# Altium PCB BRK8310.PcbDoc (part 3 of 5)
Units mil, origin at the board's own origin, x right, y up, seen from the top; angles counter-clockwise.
Board outline 6600.39 x 4492.13 mil, 4 copper layers (L1-Top, L2-GND, L3-GND, L4-BOT), stack 60.25 mil thick; 119 components, 266 nets, 1026 pads, 596 vias.
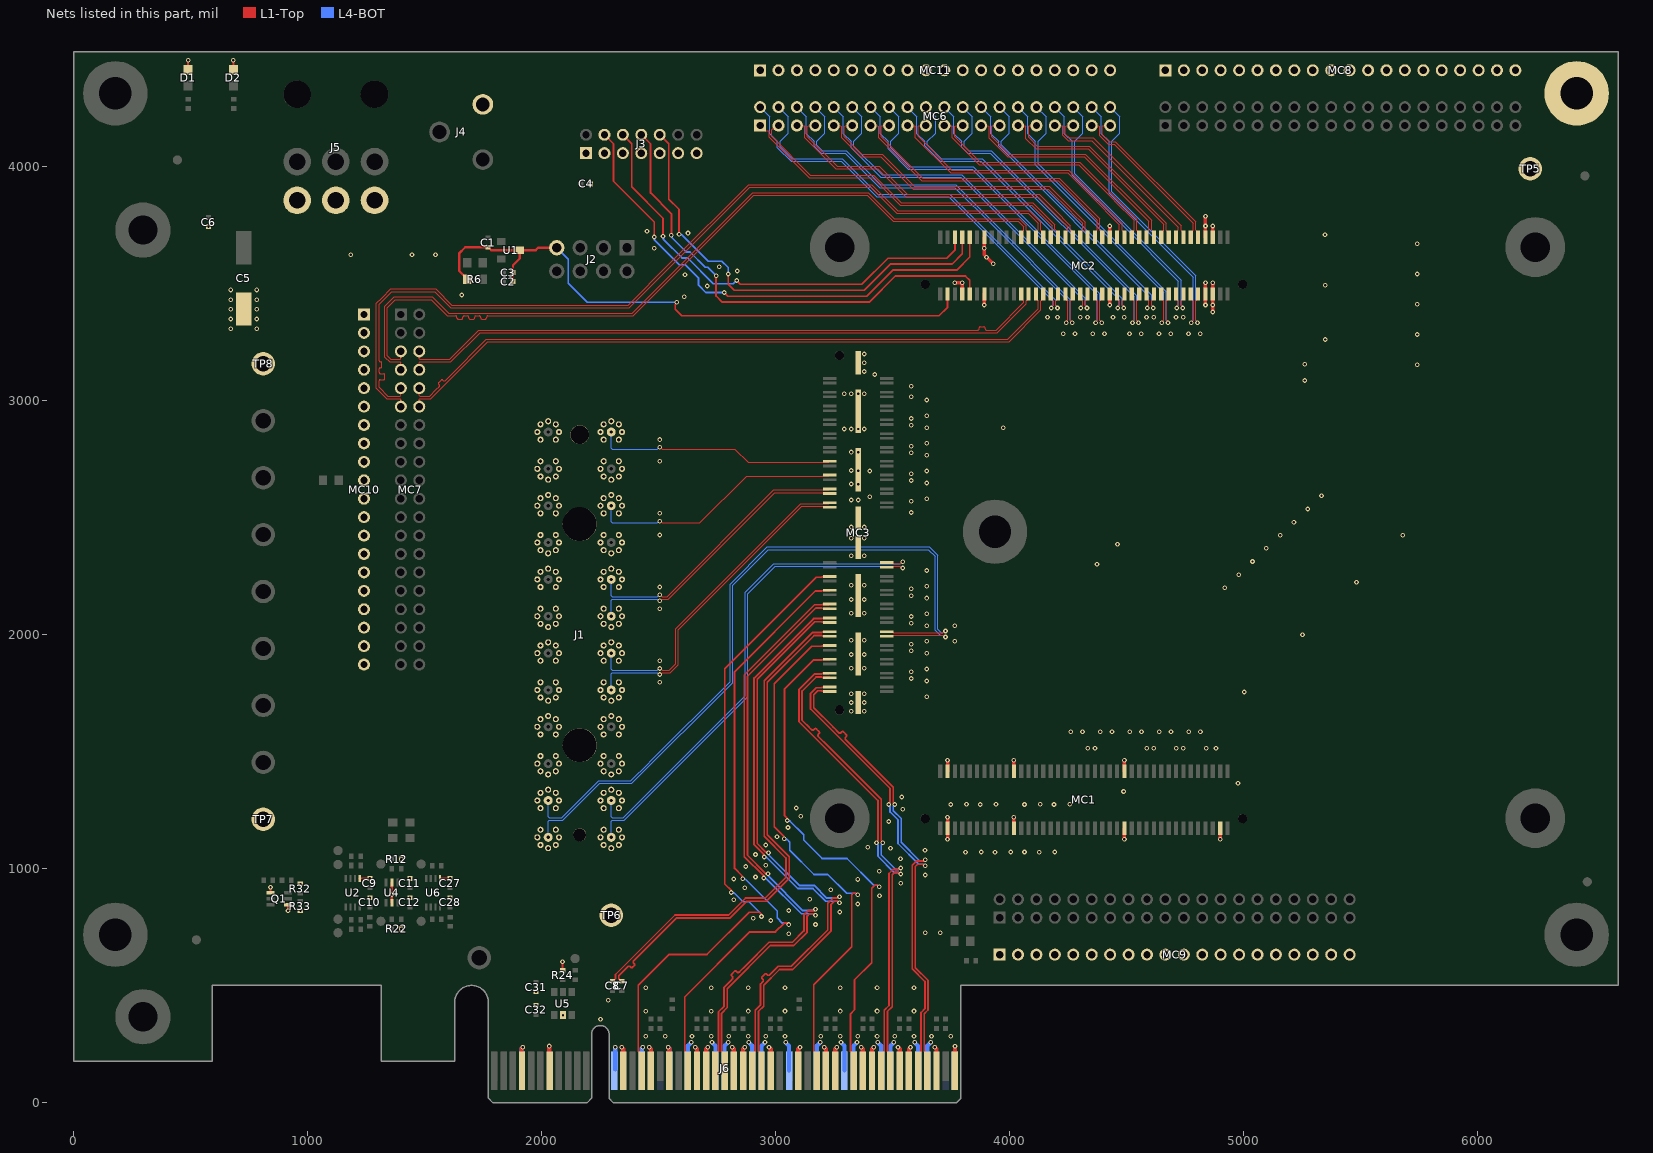
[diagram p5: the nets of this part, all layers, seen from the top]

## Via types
v1: diameter 20, hole 10, L1-Top to L4-BOT, tented both sides, 596 vias

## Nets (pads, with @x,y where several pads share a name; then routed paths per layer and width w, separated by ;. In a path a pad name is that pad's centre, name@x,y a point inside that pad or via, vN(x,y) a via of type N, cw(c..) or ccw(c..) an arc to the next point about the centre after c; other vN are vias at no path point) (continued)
B86_L1N: MC2.57 MC7.6 | length 2775
  L1-Top w5.25: MC7.6@1476.37,3212.12 1476.37,3181.45 1479.45,3178.38 1519.68,3178.38 1606.74,3178.38 1731.51,3303.15 3828.73,3303.15 3864.26,3303.15 ccw(c3864.26,3308.4) 3869.51,3308.4 3869.51,3311.84 cw(c3874.56,3311.84) 3874.56,3316.89 3889.71,3316.89 cw(c3889.71,3311.84) 3894.76,3311.84 3894.76,3308.4 ccw(c3900.01,3308.4) 3900.01,3303.15 3927.89,3303.15 3941.61,3303.15 4059.33,3420.86 4059.33,3428.29 4056.25,3431.36 4055.63,3431.36 4049.2,3437.79 MC2.57@4049.2,3457.28
B86_L1P: MC2.55 MC7.8 | length 2775
  L1-Top w5.25: MC7.8@1476.37,3133.38 1476.37,3164.05 1479.45,3167.13 1519.68,3167.13 1611.4,3167.13 1736.17,3291.9 3946.27,3291.9 4070.58,3416.2 4070.58,3428.29 4073.65,3431.36 4074.27,3431.36 4080.7,3437.79 MC2.55@4080.7,3457.28
B86_L2N: MC2.50 MC6.1 | length 1491.4
  L1-Top w5.25: MC6.1@2933.06,4177.16 2956.03,4154.2 2968.03,4154.2 2971.1,4151.12 2971.1,4127.03 3143.69,3954.44 3414.62,3954.44 3532.34,3836.72 4093.68,3836.72 4181.64,3748.75 4181.64,3748.03 4181.64,3729.19 ; MC2.50@4175.19,3700.2 4181.62,3706.63 4181.62,3729.17
B86_L2P: MC2.48 MC6.3 | length 1490.5
  L1-Top w5.25: MC6.3@3011.8,4177.16 3000.39,4177.16 2982.35,4159.13 2982.35,4131.69 3148.35,3965.69 3419.28,3965.69 3537,3847.97 4098.34,3847.97 4192.89,3753.41 4192.89,3748.03 4192.89,3733.48 4206.69,3719.68 MC2.48@4206.69,3700.2
B86_L3N: MC2.49 MC6.2 | length 1753
  L1-Top w5.25: MC2.49@4175.19,3457.28 4175.19,3437.79 4181.62,3431.36 4182.24,3431.36 4185.31,3428.29 4185.31,3408.12 4177.94,3400.74 v1(4177.94,3397.64)
  L4-BOT w5.25: MC6.2@2933.06,4255.9 2973.6,4215.36 2973.6,4142.92 3007.33,4109.19 3007.33,4082.78 3065.58,4024.53 3279.96,4024.53 3431.64,3872.86 3739.11,3872.86 4185.31,3426.65 4185.31,3408.09 4177.94,3400.71 v1(4177.94,3397.64)
B86_L3P: MC2.47 MC6.4 | length 1753.4
  L1-Top w5.25: v1(4203.94,3397.64) 4203.94,3400.74 4196.56,3408.12 4196.56,3428.29 4199.64,3431.36 4200.25,3431.36 4206.69,3437.79 MC2.47@4206.69,3457.28
  L4-BOT w5.25: MC6.4@3011.8,4255.9 3052.9,4214.8 3052.9,4143.46 3018.58,4109.14 3018.58,4087.44 3070.24,4035.78 3284.62,4035.78 3436.3,3884.11 3743.77,3884.11 4196.56,3431.31 4196.56,3408.09 4203.94,3400.71 v1(4203.94,3397.64)
B86_L4N: MC2.45 MC6.6 | length 1782.6
  L1-Top w5.25: MC2.45@4238.18,3457.28 4238.18,3437.79 4244.61,3431.36 4245.23,3431.36 4248.3,3428.29 4248.3,3345.1 4240.93,3337.72 v1(4240.93,3334.64)
  L4-BOT w5.25: MC6.6@3090.54,4255.9 3131.08,4215.36 3131.08,4142.92 3164.81,4109.19 3164.81,4088.01 3193.78,4059.03 3297.33,4059.03 3444.14,3912.23 3764.84,3912.23 3929.04,3748.03 4248.3,3428.76 4248.3,3409.45 4248.3,3345.1 4240.93,3337.72 v1(4240.93,3334.64)
B86_L4P: MC2.43 MC6.8 | length 1783.1
  L1-Top w5.25: v1(4266.93,3334.64) 4266.93,3337.72 4259.55,3345.1 4259.55,3428.29 4262.63,3431.36 4263.25,3431.36 4269.68,3437.79 MC2.43@4269.68,3457.28
  L4-BOT w5.25: MC6.8@3169.28,4255.9 3210.38,4214.8 3210.38,4143.46 3176.06,4109.14 3176.06,4092.67 3198.44,4070.28 3301.99,4070.28 3448.8,3923.48 3769.5,3923.48 3944.95,3748.03 4259.55,3433.42 4259.55,3409.45 4259.55,3345.1 4266.93,3337.72 v1(4266.93,3334.64)
B86_L5N_HDGC: MC2.58 MC7.5 | length 3437.1
  L1-Top w5.25: MC7.5@1397.63,3212.12 1397.63,3181.45 1394.55,3178.38 1368.55,3178.38 1354.26,3178.38 1352.9,3179.74 1340.16,3192.48 1340.16,3399.21 1374.04,3433.09 1527.54,3433.09 1593.68,3366.95 1596.98,3363.65 1604.33,3363.65 1632.21,3363.65 cw(c1632.21,3358.4) 1637.46,3358.4 1637.46,3354.89 ccw(c1642.51,3354.89) 1642.51,3349.84 1657.66,3349.84 ccw(c1657.66,3354.89) 1662.71,3354.89 1662.71,3358.6 cw(c1667.76,3358.6) 1667.76,3363.65 1682.91,3363.65 cw(c1682.91,3358.6) 1687.96,3358.6 1687.96,3354.89 ccw(c1693.01,3354.89) 1693.01,3349.84 1708.16,3349.84 ccw(c1708.16,3354.89) 1713.21,3354.89 1713.21,3358.6 cw(c1718.26,3358.6) 1718.26,3363.65 1733.41,3363.65 cw(c1733.41,3358.6) 1738.46,3358.6 1738.46,3355.28 ccw(c1743.51,3355.28) 1743.51,3350.23 1758.66,3350.23 ccw(c1758.66,3355.28) 1763.71,3355.28 1763.71,3358.4 cw(c1768.96,3358.4) 1768.96,3363.65 1798.73,3363.65 2391.03,3363.65 2905.84,3878.47 3391.52,3878.47 3502.27,3767.72 4035.43,3767.72 4059.33,3743.81 4059.33,3729.19 4056.25,3726.11 4055.63,3726.11 4049.2,3719.68 MC2.58@4049.2,3700.2
B86_L5P_HDGC: MC2.56 MC7.7 | length 3437.1
  L1-Top w5.25: MC7.7@1397.63,3133.38 1397.63,3164.05 1394.55,3167.13 1363.89,3167.13 1349.6,3167.13 1328.91,3187.82 1328.91,3403.87 1369.38,3444.34 1532.2,3444.34 1601.64,3374.9 1798.73,3374.9 2386.37,3374.9 2901.18,3889.72 3396.18,3889.72 3506.93,3778.97 4040.09,3778.97 4070.58,3748.47 4070.58,3729.19 4073.65,3726.11 4074.27,3726.11 4080.7,3719.68 MC2.56@4080.7,3700.2
B86_L6N_HDGC: MC2.54 MC7.9 | length 3760.2
  L1-Top w5.25: MC7.9@1397.63,3054.64 1397.63,3023.97 1394.55,3020.9 1342.13,3020.9 1304.72,3058.31 1304.72,3086.19 cw(c1309.97,3086.19) 1309.97,3091.44 1324.48,3091.44 ccw(c1324.48,3096.49) 1329.53,3096.49 1329.53,3111.64 ccw(c1324.48,3111.64) 1324.48,3116.69 1309.77,3116.69 cw(c1309.77,3121.74) 1304.72,3121.74 1304.72,3136.89 cw(c1309.77,3136.89) 1309.77,3141.94 1311.58,3141.94 ccw(c1311.58,3146.99) 1316.63,3146.99 1316.63,3162.14 ccw(c1311.58,3162.14) 1311.58,3167.19 1309.97,3167.19 cw(c1309.97,3172.44) 1304.72,3172.44 1304.72,3181.41 1304.72,3412.57 1322.7,3430.55 1326,3433.84 1359.75,3467.59 1541.83,3467.59 1611.27,3398.15 2374.27,3398.15 2889.09,3912.97 3405.81,3912.97 3516.56,3802.22 4079.39,3802.22 4122.32,3759.28 4122.32,3729.19 4119.24,3726.11 4118.63,3726.11 4112.2,3719.68 MC2.54@4112.2,3700.2
B86_L6P_HDGC: MC2.52 MC7.11 | length 3760.2
  L1-Top w5.25: MC7.11@1397.63,2975.9 1397.63,3006.57 1394.55,3009.65 1350.39,3009.65 1337.47,3009.65 1293.47,3053.65 1293.47,3181.41 1293.47,3417.23 1318.04,3441.8 1355.09,3478.84 1546.49,3478.84 1615.93,3409.4 2369.61,3409.4 2549.96,3589.75 2884.43,3924.22 3410.47,3924.22 3521.22,3813.47 4084.05,3813.47 4133.57,3763.94 4133.57,3729.19 4136.65,3726.11 4137.26,3726.11 4143.69,3719.68 MC2.52@4143.69,3700.2
B86_L7N_HDGC: MC2.42 MC6.9 | length 1329
  L1-Top w5.25: MC6.9@3248.02,4177.16 3278.69,4177.16 3281.77,4174.09 3281.77,4124.84 3363.3,4043.31 3449.51,4043.31 3587.1,3905.72 4165.14,3905.72 4259.75,3811.1 4267.71,3803.15 4311.3,3759.56 4311.3,3729.19 4308.22,3726.11 4307.6,3726.11 4301.17,3719.68 MC2.42@4301.17,3700.2
B86_L7P_HDGC: MC2.40 MC6.11 | length 1329
  L1-Top w5.25: MC6.11@3326.76,4177.16 3296.09,4177.16 3293.02,4174.09 3293.02,4129.5 3367.96,4054.56 3454.17,4054.56 3591.76,3916.97 4169.8,3916.97 4322.55,3764.22 4322.55,3729.19 4325.62,3726.11 4326.24,3726.11 4332.67,3719.68 MC2.40@4332.67,3700.2
B86_L8N_HDGC: MC2.41 MC6.10 | length 1568.6
  L1-Top w5.25: MC2.41@4301.17,3457.28 4301.17,3437.79 4307.6,3431.36 4308.22,3431.36 4311.3,3428.29 4311.3,3408.12 4303.92,3400.74 v1(4303.92,3397.64)
  L4-BOT w5.25: MC6.10@3248.02,4255.9 3288.56,4215.36 3288.56,4142.92 3322.29,4109.19 3322.29,4082.87 3449.62,3955.53 3790.29,3955.53 4311.3,3434.52 4311.3,3408.09 4303.92,3400.71 v1(4303.92,3397.64)
B86_L8P_HDGC: MC2.39 MC6.12 | length 1569
  L1-Top w5.25: v1(4329.92,3397.64) 4329.92,3400.74 4322.55,3408.12 4322.55,3428.29 4325.62,3431.36 4326.24,3431.36 4332.67,3437.79 MC2.39@4332.67,3457.28
  L4-BOT w5.25: MC6.12@3326.76,4255.9 3367.86,4214.8 3367.86,4143.46 3333.54,4109.14 3333.54,4087.53 3454.28,3966.78 3794.95,3966.78 4322.55,3439.18 4322.55,3408.09 4329.92,3400.71 v1(4329.92,3397.64)
B86_L9N: MC2.53 MC7.10 | length 2919.2
  L1-Top w5.25: MC7.10@1476.37,3054.64 1476.37,3023.97 1479.45,3020.9 1521.01,3020.9 1549.67,3049.56 1561.74,3061.63 ccw(c1558.02,3065.34) 1561.74,3069.05 1559.3,3071.48 cw(c1562.88,3075.05) 1559.3,3078.62 1570.02,3089.34 cw(c1573.59,3085.77) 1577.16,3089.34 1579.59,3086.9 ccw(c1583.3,3090.62) 1587.02,3086.9 1606.73,3106.62 1763.48,3263.37 3992.23,3263.37 4122.32,3393.46 4122.32,3428.29 4119.24,3431.36 4118.63,3431.36 4112.2,3437.79 MC2.53@4112.2,3457.28
B86_L9P: MC2.51 MC7.12 | length 2919.2
  L1-Top w5.25: MC7.12@1476.37,2975.9 1476.37,3006.57 1479.45,3009.65 1525.67,3009.65 1768.14,3252.12 3996.89,3252.12 4133.57,3388.8 4133.57,3428.29 4136.65,3431.36 4137.26,3431.36 4143.69,3437.79 MC2.51@4143.69,3457.28
B86_L10N: MC2.46 MC6.5 | length 1414.3
  L1-Top w5.25: MC6.5@3090.54,4177.16 3121.21,4177.16 3124.29,4174.09 3124.29,4125.32 3257.31,3992.29 3436.71,3992.29 3551.2,3877.81 3557.79,3871.22 4121.43,3871.22 4173.66,3818.98 4181.62,3811.02 4248.3,3744.34 4248.3,3729.19 4245.23,3726.11 4244.61,3726.11 4238.18,3719.68 MC2.46@4238.18,3700.2
B86_L10P: MC2.44 MC6.7 | length 1414.3
  L1-Top w5.25: MC6.7@3169.28,4177.16 3138.61,4177.16 3135.54,4174.09 3135.54,4129.98 3261.97,4003.54 3441.37,4003.54 3562.45,3882.47 4126.09,3882.47 4189.57,3818.98 4259.55,3749 4259.55,3729.19 4262.63,3726.11 4263.25,3726.11 4269.68,3719.68 MC2.44@4269.68,3700.2
B86_L11N: MC2.38 MC6.13 | length 1242.9
  L1-Top w5.25: MC6.13@3405.5,4177.16 3436.17,4177.16 3439.25,4174.09 3439.25,4133.86 3439.25,4124.26 3623.3,3940.22 4207.39,3940.22 4374.29,3773.32 4374.29,3729.19 4371.21,3726.11 4370.6,3726.11 4364.17,3719.68 MC2.38@4364.17,3700.2
B86_L11P: MC2.36 MC6.15 | length 1242.9
  L1-Top w5.25: MC6.15@3484.24,4177.16 3453.57,4177.16 3450.5,4174.09 3450.5,4133.86 3450.5,4128.92 3627.96,3951.47 4212.05,3951.47 4218.64,3944.88 4378.95,3784.57 4385.54,3777.98 4385.54,3729.19 4388.61,3726.11 4389.23,3726.11 4395.66,3719.68 MC2.36@4395.66,3700.2
B86_L12N: MC2.37 MC6.14 | length 1614.9
  L1-Top w5.25: MC2.37@4364.17,3457.28 4364.17,3437.79 4370.6,3431.36 4371.21,3431.36 4374.29,3428.29 4374.29,3345.1 4366.91,3337.72 v1(4366.91,3334.64)
  L4-BOT w5.25: MC6.14@3405.5,4255.9 3446.04,4215.36 3446.04,4142.92 3479.77,4109.19 3479.77,4077.5 3567.23,3990.03 3838.74,3990.03 4374.29,3454.49 4374.29,3345.1 4366.91,3337.72 v1(4366.91,3334.64)
B86_L12P: MC2.35 MC6.16 | length 1615.4
  L1-Top w5.25: v1(4392.91,3334.64) 4392.91,3337.72 4385.54,3345.1 4385.54,3428.29 4388.61,3431.36 4389.23,3431.36 4395.66,3437.79 MC2.35@4395.66,3457.28
  L4-BOT w5.25: MC6.16@3484.24,4255.9 3525.34,4214.8 3525.34,4143.46 3491.02,4109.14 3491.02,4082.16 3571.89,4001.28 3843.4,4001.28 4385.54,3459.15 4385.54,3345.1 4392.91,3337.72 v1(4392.91,3334.64)
B87_L1N: MC2.32 MC6.17 | length 1167.2
  L1-Top w5.25: MC6.17@3562.98,4177.16 3593.65,4177.16 3596.73,4174.09 3596.73,4125.99 3748.01,3974.72 4247.42,3974.72 4403.08,3819.06 4411.03,3811.1 4468.78,3753.36 4468.78,3729.19 4465.7,3726.11 4465.08,3726.11 4458.65,3719.68 MC2.32@4458.65,3700.2
B87_L1P: MC2.30 MC6.19 | length 1167.2
  L1-Top w5.25: MC6.19@3641.72,4177.16 3611.05,4177.16 3607.98,4174.09 3607.98,4130.65 3752.67,3985.97 4252.08,3985.97 4418.99,3819.06 4480.03,3758.02 4480.03,3729.19 4483.1,3726.11 4483.72,3726.11 4490.15,3719.68 MC2.30@4490.15,3700.2
B87_L2N: MC2.12 MC6.37 | length 694.6
  L1-Top w5.25: MC6.37@4350.39,4177.16 4381.06,4177.16 4384.13,4174.09 4384.13,4133.13 4419.99,4097.27 4446.68,4097.27 4783.74,3760.22 4783.74,3729.19 4780.66,3726.11 4780.04,3726.11 4773.61,3719.68 MC2.12@4773.61,3700.2
B87_L2P: MC2.10 MC6.39 | length 694.6
  L1-Top w5.25: MC6.39@4429.13,4177.16 4398.46,4177.16 4395.38,4174.09 4395.38,4137.79 4424.65,4108.52 4451.34,4108.52 4794.99,3764.88 4794.99,3729.19 4798.06,3726.11 4798.68,3726.11 4805.11,3719.68 MC2.10@4805.11,3700.2
B87_L3N: MC2.16 MC6.33 | length 778.1
  L1-Top w5.25: MC6.33@4192.91,4177.16 4223.57,4177.16 4226.65,4174.09 4226.65,4135.09 4249.02,4112.72 4351.4,4112.72 4720.74,3743.37 4720.74,3729.19 4717.67,3726.11 4717.05,3726.11 4710.62,3719.68 MC2.16@4710.62,3700.2
B87_L3P: MC2.14 MC6.35 | length 778.1
  L1-Top w5.25: MC6.35@4271.65,4177.16 4240.98,4177.16 4237.9,4174.09 4237.9,4139.75 4253.68,4123.97 4356.06,4123.97 4731.99,3748.03 4731.99,3729.19 4735.07,3726.11 4735.69,3726.11 4742.12,3719.68 MC2.14@4742.12,3700.2
B87_L4N: MC2.11 MC6.38 | length 1234.1
  L1-Top w5.25: MC2.11@4773.61,3457.28 4773.61,3437.79 4780.04,3431.36 4780.66,3431.36 4783.74,3428.29 4783.74,3345.1 4776.36,3337.72 v1(4776.36,3334.64)
  L4-BOT w5.25: MC6.38@4350.39,4255.9 4390.93,4215.36 4390.93,4142.92 4424.65,4109.19 4424.65,3888.57 4565.19,3748.03 4783.74,3529.48 4783.74,3409.45 4783.74,3345.1 4776.36,3337.72 v1(4776.36,3334.64)
B87_L4P: MC2.9 MC6.40 | length 1234.5
  L1-Top w5.25: v1(4802.36,3334.64) 4802.36,3337.72 4794.99,3345.1 4794.99,3428.29 4798.06,3431.36 4798.68,3431.36 4805.11,3437.79 MC2.9@4805.11,3457.28
  L4-BOT w5.25: MC6.40@4429.13,4255.9 4470.23,4214.8 4470.23,4143.46 4435.9,4109.14 4435.9,3893.23 4581.1,3748.03 4794.99,3534.14 4794.99,3409.45 4794.99,3345.1 4802.36,3337.72 v1(4802.36,3334.64)
B87_L5N_HDGC: MC2.31 MC6.18 | length 1405.4
  L1-Top w5.25: MC2.31@4458.65,3457.28 4458.65,3437.79 4465.08,3431.36 4465.7,3431.36 4468.78,3428.29 4468.78,3408.12 4461.4,3400.74 v1(4461.4,3397.64)
  L4-BOT w5.25: MC6.18@3562.98,4255.9 3603.52,4215.36 3603.52,4142.92 3637.25,4109.19 3637.25,4090.68 3703.4,4024.53 3876.88,4024.53 4468.78,3432.64 4468.78,3408.09 4461.4,3400.71 v1(4461.4,3397.64)
B87_L5P_HDGC: MC2.29 MC6.20 | length 1405.9
  L1-Top w5.25: v1(4487.4,3397.64) 4487.4,3400.74 4480.03,3408.12 4480.03,3428.29 4483.1,3431.36 4483.72,3431.36 4490.15,3437.79 MC2.29@4490.15,3457.28
  L4-BOT w5.25: MC6.20@3641.72,4255.9 3682.82,4214.8 3682.82,4143.46 3648.5,4109.14 3648.5,4095.34 3708.06,4035.78 3881.54,4035.78 4480.03,3437.3 4480.03,3408.09 4487.4,3400.71 v1(4487.4,3397.64)
B87_L6N_HDGC: MC2.19 MC6.30 | length 1312.3
  L1-Top w5.25: MC2.19@4647.63,3457.28 4647.63,3437.79 4654.06,3431.36 4654.68,3431.36 4657.75,3428.29 4657.75,3345.1 4650.38,3337.72 v1(4650.38,3334.64)
  L4-BOT w5.25: MC6.30@4035.43,4255.9 4075.96,4215.36 4075.96,4142.92 4109.69,4109.19 4109.69,4010.02 4657.75,3461.96 4657.75,3345.1 4650.38,3337.72 v1(4650.38,3334.64)
B87_L6P_HDGC: MC2.17 MC6.32 | length 1312.8
  L1-Top w5.25: v1(4676.38,3334.64) 4676.38,3337.72 4669,3345.1 4669,3428.29 4672.08,3431.36 4672.7,3431.36 4679.13,3437.79 MC2.17@4679.13,3457.28
  L4-BOT w5.25: MC6.32@4114.17,4255.9 4155.26,4214.8 4155.26,4143.46 4120.94,4109.14 4120.94,4014.68 4669,3466.62 4669,3345.1 4676.38,3337.72 v1(4676.38,3334.64)
B87_L7N_HDGC: MC2.27 MC6.22 | length 1447.5
  L1-Top w5.25: MC2.27@4521.65,3457.28 4521.65,3437.79 4528.08,3431.36 4528.69,3431.36 4531.77,3428.29 4531.77,3345.1 4524.39,3337.72 v1(4524.39,3334.64)
  L4-BOT w5.25: MC6.22@3720.46,4255.9 3761,4215.36 3761,4142.92 3794.73,4109.19 3794.73,4084.44 3820.14,4059.03 3917.21,4059.03 4531.77,3444.48 4531.77,3345.1 4524.39,3337.72 v1(4524.39,3334.64)
B87_L7P_HDGC: MC2.25 MC6.24 | length 1448
  L1-Top w5.25: v1(4550.39,3334.64) 4550.39,3337.72 4543.02,3345.1 4543.02,3428.29 4546.09,3431.36 4546.71,3431.36 4553.14,3437.79 MC2.25@4553.14,3457.28
  L4-BOT w5.25: MC6.24@3799.2,4255.9 3840.3,4214.8 3840.3,4143.46 3805.98,4109.14 3805.98,4089.1 3824.8,4070.28 3921.87,4070.28 4543.02,3449.14 4543.02,3345.1 4550.39,3337.72 v1(4550.39,3334.64)
B87_L8N_HDGC: MC2.24 MC6.25 | length 987.8
  L1-Top w5.25: MC6.25@3877.94,4177.16 3908.61,4177.16 3911.69,4174.09 3911.69,4133.86 3911.69,4123.74 3991.72,4043.72 4318.53,4043.72 4594.76,3767.49 4594.76,3729.19 4591.69,3726.11 4591.07,3726.11 4584.64,3719.68 MC2.24@4584.64,3700.2
B87_L8P_HDGC: MC2.22 MC6.27 | length 987.8
  L1-Top w5.25: MC6.27@3956.68,4177.16 3926.02,4177.16 3922.94,4174.09 3922.94,4133.86 3922.94,4128.4 3996.38,4054.97 4323.19,4054.97 4606.01,3772.15 4606.01,3729.19 4609.09,3726.11 4609.7,3726.11 4616.13,3719.68 MC2.22@4616.13,3700.2
B87_L9N: MC2.20 MC6.29 | length 887.8
  L1-Top w5.25: MC6.29@4035.43,4177.16 4066.09,4177.16 4069.17,4174.09 4069.17,4121.51 4112.46,4078.22 4335.27,4078.22 4657.75,3755.73 4657.75,3729.19 4654.68,3726.11 4654.06,3726.11 4647.63,3719.68 MC2.20@4647.63,3700.2
B87_L9P: MC2.18 MC6.31 | length 887.8
  L1-Top w5.25: MC6.31@4114.17,4177.16 4083.5,4177.16 4080.42,4174.09 4080.42,4126.17 4117.12,4089.47 4339.93,4089.47 4669,3760.39 4669,3729.19 4672.08,3726.11 4672.7,3726.11 4679.13,3719.68 MC2.18@4679.13,3700.2
B87_L10N: MC2.23 MC6.26 | length 1225.5
  L1-Top w5.25: MC2.23@4584.64,3457.28 4584.64,3437.79 4591.07,3431.36 4591.69,3431.36 4594.76,3428.29 4594.76,3408.12 4587.39,3400.74 v1(4587.39,3397.64)
  L4-BOT w5.25: MC6.26@3877.94,4255.9 3918.48,4215.36 3918.48,4142.92 3952.21,4109.19 3952.21,4090.3 4594.76,3447.75 4594.76,3408.09 4587.39,3400.71 v1(4587.39,3397.64)
B87_L10P: MC2.21 MC6.28 | length 1226
  L1-Top w5.25: v1(4613.39,3397.64) 4613.39,3400.74 4606.01,3408.12 4606.01,3428.29 4609.09,3431.36 4609.7,3431.36 4616.13,3437.79 MC2.21@4616.13,3457.28
  L4-BOT w5.25: MC6.28@3956.68,4255.9 3997.78,4214.8 3997.78,4143.46 3963.46,4109.14 3963.46,4094.96 4606.01,3452.41 4606.01,3408.09 4613.39,3400.71 v1(4613.39,3397.64)
B87_L11N: MC2.28 MC6.21 | length 1084.2
  L1-Top w5.25: MC6.21@3720.46,4177.16 3751.13,4177.16 3754.21,4174.09 3754.21,4133.86 3754.21,4124.73 3869.72,4009.22 4294.15,4009.22 4441.64,3861.72 4449.6,3853.77 4531.77,3771.6 4531.77,3729.19 4528.69,3726.11 4528.08,3726.11 4521.65,3719.68 MC2.28@4521.65,3700.2
B87_L11P: MC2.26 MC6.23 | length 1084.2
  L1-Top w5.25: MC6.23@3799.2,4177.16 3768.53,4177.16 3765.46,4174.09 3765.46,4133.86 3765.46,4129.39 3874.38,4020.47 4298.81,4020.47 4457.55,3861.72 4543.02,3776.26 4543.02,3729.19 4546.09,3726.11 4546.71,3726.11 4553.14,3719.68 MC2.26@4553.14,3700.2
B87_L12N: MC2.15 MC6.34 | length 1147.2
  L1-Top w5.25: MC2.15@4710.62,3457.28 4710.62,3437.79 4717.05,3431.36 4717.67,3431.36 4720.75,3428.29 4720.75,3408.12 4713.37,3400.74 v1(4713.37,3397.64)
  L4-BOT w5.25: MC6.34@4192.91,4255.9 4233.45,4215.36 4233.45,4142.92 4267.17,4109.19 4267.17,3965.63 4484.77,3748.03 4720.75,3512.06 4720.75,3409.45 4720.75,3408.09 4713.37,3400.71 v1(4713.37,3397.64)
B87_L12P: MC2.13 MC6.36 | length 1147.7
  L1-Top w5.25: v1(4739.37,3397.64) 4739.37,3400.74 4732,3408.12 4732,3428.29 4735.07,3431.36 4735.69,3431.36 4742.12,3437.79 MC2.13@4742.12,3457.28
  L4-BOT w5.25: MC6.36@4271.65,4255.9 4312.75,4214.8 4312.75,4143.46 4278.42,4109.14 4278.42,3970.29 4500.68,3748.03 4732,3516.72 4732,3409.45 4732,3408.09 4739.37,3400.71 v1(4739.37,3397.64)
DGND: C4.2 C5.2 C6.1 C9.1 C10.1 C11.1 C12.1 C27.1 C28.1 C31.1 C32.1 D1.1 D2.1 J1.GND1 J3.1 J3.3 J3.5 J3.7 J3.9 J3.11 J3.13 J4.2 J5.4 J5.5 J5.6 J6.A4 J6.A12 J6.A15 J6.A18 J6.A20 J6.A23 J6.A24 J6.A27 J6.A28 J6.A31 J6.A34 J6.A37 J6.A38 J6.A41 J6.A42 J6.A45 J6.A46 J6.A49 J6.B4 J6.B7 J6.B13 J6.B16 J6.B18 J6.B21 J6.B22 J6.B25 J6.B26 J6.B29 J6.B32 J6.B35 J6.B36 J6.B39 J6.B40 J6.B43 J6.B44 J6.B47 J6.B49 MC1.3 MC1.29 MC1.30 MC1.59 MC1.60 MC1.77 MC1.78 MC2.5 MC2.6 MC2.7 MC2.8 MC2.33 MC2.34 MC2.67 MC2.68 MC2.73 MC3.0 MC8.1 MC8.2 MC8.3 MC8.4 MC8.5 MC8.6 MC8.7 MC8.8 MC8.9 MC8.10 MC8.11 MC8.12 MC8.13 MC8.14 MC8.15 MC8.16 MC8.17 MC8.18 MC8.19 MC8.20 MC9.1 MC9.2 MC9.3 MC9.4 MC9.5 MC9.6 MC9.7 MC9.8 MC9.9 MC9.10 MC9.11 MC9.12 MC9.13 MC9.14 MC9.15 MC9.16 MC9.17 MC9.18 MC9.19 MC9.20 MC10.1 MC10.2 MC10.3 MC10.4 MC10.5 MC10.6 MC10.7 MC10.8 MC10.9 MC10.10 MC10.11 MC10.12 MC10.13 MC10.14 MC10.15 MC10.16 MC10.17 MC10.18 MC10.19 MC10.20 MC11.1 MC11.2 MC11.3 MC11.4 MC11.5 MC11.6 MC11.7 MC11.8 MC11.9 MC11.10 MC11.11 MC11.12 MC11.13 MC11.14 MC11.15 MC11.16 MC11.17 MC11.18 MC11.19 MC11.20 pad.MH@6423.23,4314.96 Q1.1 Q1.4 R12.1 R22.1 R24.1 R32.1 R33.1 TP5.1 TP6.1 TP7.1 TP8.1 U2.1 U4.2 U4.5 U5.2 U6.1 | length 5543.1
  L1-Top w8: D1.1@488.36,4415.31 v1(488.36,4456.65) ; D2.1@681.88,4415.31 v1(681.88,4456.65) ; Q1.4@840.6,898.41 v1(840.6,921.24) ; v1(915.4,820.65) Q1.1@915.4,847.23 ; U2.1@1221.6,959.43 1221.99,959.82 1264.51,959.82 v1(1264.9,959.43) ; U6.1@1565.1,959.43 v1(1608.41,959.43) ; R24.1@2088.57,566.14 v1(2088.57,602.6)
  L1-Top w10: U4.5@1359.39,855.1 v1(1359.39,890.53) U4.2@1359.39,941.71
  L1-Top w15: v1(3734.24,1126.36) MC1.77@3734.24,1173.82 v1(3734.24,1221.27) ; MC1.78@3734.24,1416.73 v1(3734.24,1464.19) ; v1(3765.46,3504.74) v1(3797.24,3504.74) MC2.73@3797.24,3457.28 ; v1(3891.72,3409.83) MC2.67@3891.72,3457.28 ; MC2.68@3891.72,3700.2 v1(3891.72,3652.74) 3891.72,3624.38 v1(3929.65,3586.46) ; MC1.59@4017.71,1173.82 v1(4017.71,1221.27) ; MC1.60@4017.71,1416.73 v1(4017.71,1464.19) ; v1(4427.16,3409.83) MC2.33@4427.16,3457.28 ; MC2.34@4427.16,3700.2 v1(4427.16,3747.65) ; v1(4490.15,1126.36) MC1.29@4490.15,1173.82 ; MC1.30@4490.15,1416.73 v1(4490.15,1464.19) ; v1(4836.61,3409.83) MC2.7@4836.61,3457.28 v1(4836.61,3504.74) ; MC2.8@4836.61,3700.2 v1(4836.61,3747.65) v1(4836.61,3789.02) ; v1(4868.1,3380.44) v1(4868.1,3409.83) MC2.5@4868.1,3457.28 v1(4868.1,3504.74) ; MC2.6@4868.1,3700.2 v1(4868.1,3747.65) ; v1(4899.6,1126.36) MC1.3@4899.6,1173.82
  L1-Top w18: J6.B4@1913.38,137.79 1913.38,232.25 1918.38,237.25 v1(1918.38,237.79) ; J6.B7@2031.49,137.79 v1(2031.49,242.76) ; v1(2341.22,237.81) 2341.22,237.27 2348.42,230.07 J6.B13@2348.42,137.79 ; v1(2459.33,237.81) 2459.33,237.27 2466.53,230.07 J6.B16@2466.53,137.79 ; v1(2540.27,237.79) 2540.27,237.25 2545.05,232.47 2545.05,221.74 2545.27,221.52 J6.B18@2545.27,137.79 ; v1(2656.18,237.81) 2656.18,237.27 2663.38,230.07 J6.B21@2663.38,137.79 ; J6.B22@2702.75,137.79 2702.75,230.07 2709.95,237.27 v1(2709.95,237.81) ; v1(2813.66,237.81) 2813.66,237.27 2820.86,230.07 J6.B25@2820.86,137.79 ; J6.B26@2860.23,137.79 2860.23,230.07 2867.43,237.27 v1(2867.43,237.81) ; v1(2971.14,237.81) 2971.14,237.27 2978.34,230.07 J6.B29@2978.34,137.79 ; J6.B32@3096.45,137.79 3096.45,230.07 3103.65,237.27 v1(3103.65,237.81) ; v1(3207.36,237.81) 3207.36,237.27 3214.56,230.07 J6.B35@3214.56,137.79 ; J6.B36@3253.93,137.79 3253.93,230.07 3261.13,237.27 v1(3261.13,237.81) ; v1(3364.84,237.81) 3364.84,237.27 3372.04,230.07 J6.B39@3372.04,137.79 ; J6.B40@3411.41,137.79 3411.41,230.07 3418.61,237.27 v1(3418.61,237.81) ; v1(3522.32,237.81) 3522.32,237.27 3529.52,230.07 J6.B43@3529.52,137.79 ; J6.B44@3568.89,137.79 3568.89,230.07 3576.09,237.27 v1(3576.09,237.81) ; v1(3679.8,237.81) 3679.8,237.27 3687,230.07 J6.B47@3687,137.79 ; J6.B49@3765.74,137.79 3765.96,138.01 3765.96,242.46 v1(3766.18,242.68)
  L4-BOT w18: J6.A4@1913.38,137.79 1913.38,232.79 v1(1918.38,237.79) ; J6.A12@2314.05,142.79 v1(2314.05,237.79) ; J6.A15@2427.16,137.79 2427.16,232.79 v1(2432.16,237.79) ; v1(2540.27,237.79) 2545.27,232.79 J6.A18@2545.27,137.79 ; J6.A20@2624.01,137.79 2624.01,243.81 v1(2638.76,258.56) ; v1(2727.36,258.56) 2742.12,243.81 J6.A23@2742.12,137.79 ; J6.A24@2781.49,137.79 2781.49,243.81 v1(2796.24,258.56) ; v1(2884.84,258.56) 2899.6,243.81 J6.A27@2899.6,137.79 ; J6.A28@2938.97,137.79 2938.97,243.81 v1(2953.72,258.56) ; v1(3042.32,258.56) 3057.08,243.81 J6.A31@3057.08,137.79 ; J6.A34@3175.19,137.79 3175.19,243.81 v1(3189.94,258.56) ; v1(3278.54,258.56) 3293.3,243.81 J6.A37@3293.3,137.79 ; J6.A38@3332.67,137.79 3332.67,243.81 v1(3347.42,258.56) ; v1(3436.03,258.56) 3450.78,243.81 J6.A41@3450.78,137.79 ; J6.A42@3490.15,137.79 3490.15,243.81 v1(3504.9,258.56) ; v1(3593.51,258.56) 3608.26,243.81 J6.A45@3608.26,137.79 ; J6.A46@3647.63,137.79 3647.63,243.81 v1(3662.38,258.56) ; J6.A49@3765.74,137.79 3765.96,138.01 3765.96,242.46 v1(3766.18,242.68)
  other v1: 2444.87,285.27 2527.55,285.27 2641.72,285.27 2724.4,285.27 2799.2,285.27 2881.88,285.27 2956.69,285.27 3039.36,285.27 3192.91,285.27 3275.58,285.27 3350.39,285.27 3433.06,285.27 3507.87,285.27 3590.54,285.27 3665.35,285.27 3748.02,285.27 2250.65,357.48 2090.54,375.2 2444.87,391.93 2724.4,391.93 2881.88,392.32 3039.36,392.32 3275.58,392.32 3433.06,392.32 3590.54,392.32 1975.47,417.08 2283.67,439.01 1975.47,475.47 2444.87,492.13 2724.4,492.13 2881.88,492.52 3039.36,492.52 3275.58,492.52 3433.06,492.52 3590.54,492.52 3055.6,722.39 3638.86,726.83 3702.75,726.83 1398.76,744.86 3170.16,762.57 2978.38,779.21 2903.91,789.69 3272.92,815.92 968.55,821.63 3055.6,822.23 3350.87,849.77 2820.35,868.56 3145.11,870.08 1264.9,876.75 1436.16,876.75 1608.41,876.75 3443.39,884.7 3235.68,910.42 2866.81,919 968.55,935.81 3534.15,938.35 3349.9,955.07 2820.92,957.09 1436.16,959.43 2913.38,965.16 3638.86,974.07 3442.42,990 2871.06,1010.33 2957.81,1015.49 1398.76,1040.98 3533.18,1043.65 2913.09,1061.72 3810.82,1071.78 3877.94,1072.05 3936.8,1071.78 4003.93,1072.05 4062.98,1072.05 4125.78,1071.78 4192.91,1072.05 3637.89,1079.36 3490.15,1088.58 3393.08,1092.08 2957.69,1102.43 3005.24,1137.26 3052.38,1176.84 3482.5,1202.57 3107.42,1225.01 3543.3,1254.85 3087.38,1260.64 3748.02,1275.59 3815.15,1275.85 3874.01,1275.59 3941.14,1275.85 4062.98,1275.59 4130.11,1275.85 4188.97,1275.59 4256.1,1275.85 3538.06,1307.01 4486.59,1330.71 4975.39,1366.73 4333.05,1515.75 4364.17,1515.75 4585.02,1515.75 4616.13,1515.75 4711,1515.75 4742.12,1515.75 4839.35,1515.75 4881.88,1515.75 4260.62,1586.61 4311.02,1586.61 4386.61,1586.61 4437,1586.61 4512.59,1586.61 4562.98,1586.61 4638.57,1586.61 4688.97,1586.61 4764.56,1586.61 4814.95,1586.61 3323.02,1674.01 3378.34,1674.01 3323.02,1711.02 3378.34,1711.02 3645.66,1736.22 3323.02,1748.03 3378.34,1748.03 5002.95,1755.91 2504.63,1797.15 3645.66,1803.15 3578.73,1813.77 3578.73,1842.52 3645.66,1854.33 3323.02,1857.66 3378.34,1857.66 2504.63,1890.04 3323.02,1916.35 3378.34,1916.35 3645.66,1921.26 3578.73,1931.88 3578.73,1960.63 3645.66,1972.44 3764.56,1972.44 3323.02,1977.13 3378.34,1977.13 5250.98,2000.98 3645.66,2039.37 3764.56,2039.37 3578.73,2049.99 3578.73,2078.74 3645.66,2090.55 3323.02,2092.52 3378.34,2092.52 2504.63,2112.11 3323.02,2151.21 3378.34,2151.21 3645.66,2157.48 3578.73,2168.1 3578.73,2196.85 4919.29,2201.77 2504.63,2205 3645.66,2208.66 3323.02,2211.99 3378.34,2211.99 5482.28,2225.39 4978.35,2257.87 3645.66,2275.59 4373.22,2301.53 5037.4,2313.98 3323.02,2338.58 3378.34,2338.58 5096.46,2370.08 4460.38,2387.03 3323.02,2412.98 3378.34,2412.98 5155.51,2426.18 5679.79,2426.18 2504.63,2427.07 3323.02,2461.42 3378.34,2461.42 5214.57,2482.28 2504.63,2519.96 3578.73,2523.62 5273.62,2538.39 3578.73,2570.86 3322.48,2576.87 3352.35,2576.87 3645.66,2582.68 3401.57,2590.55 5332.68,2594.49 3352.35,2644.36 3323.02,2645.06 3645.66,2649.61 3578.73,2660.23 3578.73,2688.98 3401.57,2700.79 3645.66,2700.79 3352.35,2701.94 3323.02,2702.64 2504.63,2742.03 3645.66,2767.72 3578.73,2778.34 3323.02,2781.49 3352.35,2780.8 3578.73,2807.09 3645.66,2818.9 2504.63,2834.92 3292.51,2879.92 3323.02,2879.92 3352.35,2879.92 3378.34,2879.92 3645.66,2885.83 3972.09,2885.83 3578.73,2896.45 3578.73,2925.2 3645.66,2937.01 3645.66,3003.94 3578.73,3017.72 3292.51,3031.49 3323.02,3031.49 3352.35,3031.49 3378.34,3031.49 3578.73,3062.99 5261.52,3087.17 3423.6,3112.99 3378.34,3125.98 5742.12,3154.49 5261.52,3156.57 3378.34,3162.99 3378.34,3200.39 5348.43,3262.8 5742.12,3283.78 4228.34,3287.4 4278.73,3287.4 4354.32,3287.4 4404.72,3287.4 4511.8,3287.4 4562.2,3287.4 4637.79,3287.4 4688.18,3287.4 4763.77,3287.4 4814.17,3287.4 670.87,3308.5 781.47,3308.5 670.87,3350.03 781.47,3350.03 4161.41,3358.27 4203.94,3358.27 4301.17,3358.27 4332.29,3358.27 4441.64,3358.27 4489.77,3358.27 4584.64,3358.27 4615.76,3358.27 4710.62,3358.27 4741.74,3358.27 670.87,3391.56 781.47,3391.56 5742.12,3413.07 670.87,3433.09 781.47,3433.09 2608.27,3444.88 1657.66,3452.93 670.87,3474.62 781.47,3474.62 2706.69,3491.14 5348.43,3494.4 2612.2,3539.37 5742.12,3542.36 2835.63,3555.12 2758.73,3574 3901.03,3614.1 1182.88,3624.53 1445.44,3624.53 1545.56,3624.53 2480.31,3652.56 5742.12,3671.65 5347.63,3710.19 2625,3717.52 2449.8,3725.39 575.78,3744.68 2209.2,3927.72
GNDADC: C1.2 C2.1 C3.2 J2.7 MC2.77 R6.1 U1.3 | length 2657.9
  L1-Top w8: v1(2576.58,3421.97) 2576.58,3418.72 2570.52,3412.66 2570.52,3391.45 2598.02,3363.95 3697.61,3363.95 3734.24,3400.58 3734.24,3409.45 MC2.77@3734.24,3457.28
  L1-Top w10: R6.1@1680.8,3520.41 1680.8,3522.38 1646.59,3556.59 1646.59,3630.16 1673.04,3656.61 C1.2@1770.65,3656.61 1771.24,3656.61 1783.64,3644.21 U1.3@1905.9,3644.21 ; C2.1@1876.61,3509.73 C3.2@1876.61,3548.96 1876.61,3580.21 1905.9,3609.5 U1.3@1905.9,3644.21 ; J2.7@2063.92,3654.69 1983.94,3654.69 1973.46,3644.21 U1.3@1905.9,3644.21
  L4-BOT w7.5: J2.7@2063.92,3654.69 2113.1,3605.51 2113.1,3502.28 2193.47,3421.91 2576.53,3421.91 v1(2576.58,3421.97)
JTAG_TCK: J3.6 MC2.76 | length 1973.8
  L1-Top w7.5: J3.6@2346.6,4137.79 2384.7,4099.7 2384.7,3914.76 2518.25,3781.2 v1(2518.25,3704.19) ; v1(2832.68,3514.76) 2848.43,3499.02 3368.11,3499.02 3479.46,3610.37 3731.43,3610.37 3765.74,3644.68 MC2.76@3765.74,3700.2
  L4-BOT w7.5: v1(2518.25,3704.19) 2519.93,3702.51 2519.93,3690.82 2599.62,3611.13 2623.12,3611.13 2733.27,3500.98 2818.9,3500.98 2831.69,3513.78 v1@2835.63,3513.78
JTAG_TDI: J3.10 MC2.74 | length 1946.9
  L1-Top w7.5: J3.10@2504.08,4137.79 2543.14,4098.73 2543.14,3861.98 2586.81,3818.31 v1(2586.81,3712.01) ; v1(2796.65,3542.85) 2796.65,3499.14 2822.28,3473.52 3378.67,3473.52 3490.03,3584.87 3753.18,3584.87 3797.24,3628.94 MC2.74@3797.24,3701.77
  L4-BOT w7.5: v1@2587.6,3710.63 2598.3,3710.63 2711.49,3597.44 2769.69,3597.44 2796.65,3570.47 v1(2796.65,3542.85)
JTAG_TDO: J3.8 MC2.71 | length 2042.3
  L1-Top w7.5: J3.8@2425.34,4137.79 2465.07,4098.07 2465.07,3889.21 2553.97,3800.31 v1(2553.97,3707.84) ; v1(2746.32,3535.64) 2745.08,3534.4 2745.08,3448.82 2771.38,3422.52 3399.8,3422.52 3511.15,3533.87 3810.62,3533.87 3828.73,3515.76 3828.73,3463.59 MC2.71@3830.71,3461.61
  L4-BOT w7.5: v1(2553.97,3707.84) 2556.36,3705.45 2556.36,3697.04 2616.77,3636.63 2633.68,3636.63 2698.37,3571.94 2710.02,3571.94 v1(2746.32,3535.64)
JTAG_TMS: J3.4 MC2.72 | length 2153.3
  L1-Top w7.5: J3.4@2267.86,4137.79 2306.55,4099.11 2306.55,3939.29 2480.98,3764.86 v1(2480.98,3700.8) ; v1(2779.33,3463.69) 2795,3448.02 3389.23,3448.02 3500.59,3559.37 3772.95,3559.37 3828.73,3615.15 3828.73,3690.95 MC2.72@3824.8,3694.88
  L4-BOT w7.5: v1(2480.98,3700.8) 2482.24,3699.54 2482.24,3687.05 2587.6,3581.69 2612.86,3581.69 2670.28,3524.28 2670.28,3494.09 2700.68,3463.69 v1(2779.33,3463.69)
MGT_REFCLK0N_224_C: J1.A02 MC3.20 | length 3087
  L1-Top w5.25: MC3.20@3474.01,2013.78 3477.29,2010.5 3502.06,2010.5 3503,2009.56 3542.49,2009.56 3714.74,2009.56 3722.11,2016.94 v1(3725.19,2016.94)
  L4-BOT w5.25: J1.A02@2027.27,1292.41 2027.27,1223.45 2031.42,1219.3 2084.78,1219.3 2242.44,1376.96 2380.53,1376.96 2456.1,1452.53 2464.05,1460.49 2804.51,1800.94 2804.51,2216.51 2963.87,2375.87 3656.99,2375.87 3692.57,2340.3 3692.57,2024.31 3707.31,2009.56 3714.74,2009.56 3722.11,2016.94 v1(3725.19,2016.94)
MGT_REFCLK0N_226_C: J1.B02 MC3.40 | length 2102.7
  L1-Top w5.25: MC3.40@3474.01,2309.05 3477.29,2305.77 3502.06,2305.77 3503,2304.84 3532.85,2304.84 3540.22,2312.21 v1(3543.3,2312.21)
  L4-BOT w5.25: J1.B02@2296.96,1292.41 2296.96,1223.45 2301.11,1219.3 2348.5,1219.3 2868.96,1739.75 2868.96,2181.7 2992.09,2304.84 3532.85,2304.84 3540.22,2312.21 v1(3543.3,2312.21)
MGT_REFCLK0P_224_C: J1.A01 MC3.18 | length 3087
  L1-Top w5.25: MC3.18@3474.01,1994.09 3477.29,1997.37 3502.06,1997.37 3503,1998.31 3547.15,1998.31 3714.74,1998.31 3722.11,1990.94 v1(3725.19,1990.94)
  L4-BOT w5.25: J1.A01@2027.27,1134.93 2027.27,1203.9 2031.42,1208.05 2089.44,1208.05 2247.1,1365.71 2385.19,1365.71 2815.76,1796.28 2815.76,2211.85 2968.53,2364.62 3652.33,2364.62 3681.32,2335.64 3681.32,2019.65 3702.65,1998.31 3714.74,1998.31 3722.11,1990.94 v1(3725.19,1990.94)
MGT_REFCLK0P_226_C: J1.B01 MC3.38 | length 2102.7
  L1-Top w5.25: MC3.38@3474.01,2289.37 3477.29,2292.65 3502.06,2292.65 3503,2293.59 3532.85,2293.59 3540.22,2286.21 v1(3543.3,2286.21)
  L4-BOT w5.25: J1.B01@2296.96,1134.93 2296.96,1203.9 2301.11,1208.05 2353.16,1208.05 2880.21,1735.09 2880.21,2177.04 2996.75,2293.59 3532.85,2293.59 3540.22,2286.21 v1(3543.3,2286.21)
MGT_REFCLK1N_225_C: C8.2 MC3.19 | length 2180.8
  L1-Top w7.5: C8.2@2302.25,520.22 2308.74,526.71 2310.79,526.71 2315.18,531.1 2315.18,548.91 2569.49,803.22 2798.27,803.22 2870.42,875.37 2954.07,875.37 3043.86,965.16 3043.86,1046.09 2950.34,1139.61 2950.34,1803.39 3157.64,2010.69 3196.93,2010.69 3198.41,2012.16 3229.08,2012.16 MC3.19@3230.7,2013.78
MGT_REFCLK1P_225_C: C7.2 MC3.17 | length 2181.1
  L1-Top w7.5: C7.2@2341.62,520.22 2335.13,526.71 2333.08,526.71 2328.68,531.1 2328.68,543.32 2350.47,565.1 2367.61,582.25 cw(c2372.92,576.95) 2378.22,582.25 2381.56,578.91 ccw(c2384.46,581.81) 2387.36,578.91 2396.06,587.6 ccw(c2393.16,590.5) 2396.06,593.4 2392.72,596.75 cw(c2398.02,602.05) 2392.72,607.35 2420.47,635.1 2575.09,789.72 2803.86,789.72 2876.01,861.87 2959.66,861.87 3057.36,959.57 3057.36,1051.68 2963.84,1145.2 2963.84,1797.79 3163.24,1997.19 3196.93,1997.19 3198.41,1995.71 3229.08,1995.71 MC3.17@3230.7,1994.09
MGT_RXN0_224: J6.B46 MC3.3 | length 2004.9
  L1-Top w7.5: MC3.3@3230.7,1777.56 3229.08,1775.94 3198.41,1775.94 3196.93,1774.47 3173.43,1774.47 3148.95,1749.99 3148.95,1683.42 3488.75,1343.62 3488.75,1284.43 3482.5,1278.18 v1(3482.5,1275.59) ; v1(3638.38,1013.72) 3638.13,1013.72 3631.88,1019.97 3606.29,1019.97 3596.66,1010.33 3596.66,578.28 3650.79,524.14 3650.79,397.01 3634.7,380.91 3634.7,235.1 3634.7,219.63 3647.63,206.69 J6.B46@3647.63,137.79
  L4-BOT w7.5: v1(3482.5,1275.59) 3482.5,1272.21 3488.75,1265.96 3488.75,1243.2 3522.32,1209.62 3522.32,1108.75 3611.11,1019.97 3628.75,1019.97 3635,1013.72 v1(3638.38,1013.72)
MGT_RXN0_225: J6.B28 MC3.23 | length 2536.8
  L1-Top w7.5: J6.B28@2938.97,137.79 2938.97,206.69 2926.03,219.63 2926.03,235.1 2926.03,390.84 2948.56,413.37 2948.56,502.69 3016.03,570.16 3072.58,570.16 3235.68,733.26 3235.68,847.35 3250.15,861.82 3262.8,861.82 3269.05,855.57 v1(3272.43,855.57) ; v1(2950.42,1051.09) 2948.11,1053.4 2948.11,1062.24 2907.44,1102.91 2907.44,1815.64 3161.54,2069.74 3196.93,2069.74 3198.41,2071.21 3229.08,2071.21 MC3.23@3230.7,2072.83
  L4-BOT w7.5: v1(2950.42,1051.09) 2952.81,1048.7 2961.65,1048.7 3094.29,916.06 3158.79,916.06 3213.03,861.82 3262.8,861.82 3269.05,855.57 v1(3272.43,855.57)
MGT_RXN0_226: J1.B06 MC3.43 | length 1394.6
  L1-Top w5.25: v1(2504.63,1856.59) 2507.71,1856.59 2515.08,1849.22 2543.83,1849.22 2571.55,1876.94 2571.55,2026.44 3105.86,2560.74 3201.71,2560.74 3202.64,2561.68 3227.42,2561.68 MC3.43@3230.7,2564.96
  L4-BOT w5.25: J1.B06@2296.96,1922.33 2296.96,1853.37 2301.11,1849.22 2425.59,1849.22 2494.18,1849.22 2501.56,1856.59 v1(2504.63,1856.59)
MGT_RXN1_224: J6.B42 MC3.7 | length 2039.9
  L1-Top w7.5: MC3.7@3230.7,1836.61 3229.08,1834.99 3198.41,1834.99 3196.93,1833.52 3166.83,1833.52 3098.79,1765.48 3098.79,1630.03 3436.85,1291.98 3436.85,1121.06 3430.6,1114.81 v1(3430.6,1111.43) ; J6.B42@3490.15,137.79 3490.15,206.69 3477.21,219.63 3477.21,235.1 3477.21,390.61 3497.37,410.76 3497.37,974.63 3506.99,984.25 3524.03,984.25 3530.28,978 v1(3533.67,978)
  L4-BOT w7.5: v1(3430.6,1111.43) 3430.6,1108.05 3436.85,1101.8 3436.85,1053.8 3506.39,984.25 3524.03,984.25 3530.28,978 v1(3533.67,978)
MGT_RXN1_225: J6.B24 MC3.27 | length 2606.5
  L1-Top w7.5: J6.B24@2781.49,137.79 2781.49,206.69 2768.55,219.63 2768.55,235.1 2768.55,383.5 2792.56,407.5 2792.56,488.43 2976.75,672.62 3077.09,672.62 3133.85,729.38 3133.85,798.23 3144.09,808.46 3160.04,808.46 3166.29,802.21 v1(3169.67,802.21) 3169.67,804.07 v1@3165.28,808.46 ; v1(2948.47,960.94) 2948.11,961.29 2948.11,970.13 2865.53,1052.72 2865.53,1828.88 3165.45,2128.8 3196.93,2128.8 3198.41,2130.27 3229.08,2130.27 MC3.27@3230.7,2131.89
  L4-BOT w7.5: v1(2948.47,960.94) 2950.86,958.55 2959.7,958.55 3109.78,808.46 3160.04,808.46 3166.29,802.21 v1(3169.67,802.21)
MGT_RXN1_226: J1.B08 MC3.47 | length 1201
  L1-Top w5.25: v1(2504.63,2171.56) 2507.71,2171.56 2515.08,2164.18 2535.63,2164.18 2991.25,2619.8 3201.71,2619.8 3202.64,2620.73 3227.42,2620.73 MC3.47@3230.7,2624.01
  L4-BOT w5.25: J1.B08@2296.96,2237.3 2296.96,2168.33 2301.11,2164.18 2425.59,2164.18 2494.18,2164.18 2501.56,2171.56 v1(2504.63,2171.56)
MGT_RXN2_224: J6.B38 MC3.11 | length 2200.2
  L1-Top w7.5: v1(3049.71,1206.63) 3047.32,1209.02 3047.32,1217.86 3037.77,1227.41 3037.77,1769.96 3160.38,1892.58 3196.93,1892.58 3198.41,1894.05 3229.08,1894.05 MC3.11@3230.7,1895.67 ; J6.B38@3332.67,137.79 3332.67,206.69 3319.73,219.63 3319.73,235.1 3319.73,381.3 3336.62,398.18 3336.62,525.7 3409.94,599.02 3409.94,917.79 3422.75,930.6 3433.27,930.6 3439.52,924.35 v1(3442.91,924.35)
  L4-BOT w7.5: v1(3049.71,1206.63) 3052.11,1204.24 3060.94,1204.24 3119.17,1146.01 3119.17,1123.48 3198.06,1044.59 3304.25,1044.59 3418.24,930.6 3433.27,930.6 3439.52,924.35 v1(3442.91,924.35)
MGT_RXN2_225: J6.B20 MC3.31 | length 2643.5
  L1-Top w7.5: J6.B20@2624.01,137.79 2624.01,206.69 2611.07,219.63 2611.07,235.1 2611.07,247.41 2611.07,452.51 2889.28,730.71 2998.53,730.71 3036.11,768.29 3050.72,768.29 3055.11,763.9 v1(3055.11,762.04) ; v1(2859.44,957.76) 2859.99,958.3 2859.99,963.53 2855.91,967.61 2855.91,970.13 2823.94,1002.1 2823.94,1842.45 3169.35,2187.85 3196.93,2187.85 3198.41,2189.32 3229.08,2189.32 MC3.31@3230.7,2190.94
  L4-BOT w7.5: v1(2859.44,957.76) 2861.84,955.37 2870.67,955.37 3006,820.04 3006,790.56 3028.27,768.29 3045.48,768.29 3051.73,762.04 v1(3055.11,762.04)
MGT_RXN2_226: J1.B10 MC3.51 | length 1095
  L1-Top w5.25: v1(2504.63,2486.52) 2507.71,2486.52 2515.08,2479.14 2675.97,2479.14 2875.68,2678.85 3201.71,2678.85 3202.64,2679.79 3227.42,2679.79 MC3.51@3230.7,2683.07
  L4-BOT w5.25: J1.B10@2296.96,2552.26 2296.96,2483.29 2301.11,2479.14 2425.59,2479.14 2494.18,2479.14 2501.56,2486.52 v1(2504.63,2486.52)
MGT_RXN3_224: J6.B34 MC3.15 | length 2274
  L1-Top w7.5: v1(3036.83,1128.6) 3034.44,1130.99 3034.44,1139.83 2993.58,1180.69 2993.58,1791.47 3153.74,1951.63 3196.93,1951.63 3198.41,1953.1 3229.08,1953.1 MC3.15@3230.7,1954.72 ; J6.B34@3175.19,137.79 3175.19,206.69 3162.25,219.63 3162.25,505.02 3324.52,667.28 3324.52,889.9 3330.28,895.67 3344.41,895.67 3350.39,889.69 v1(3350.39,889.42)
  L4-BOT w7.5: v1(3036.83,1128.6) 3039.22,1126.21 3048.06,1126.21 3059.79,1114.48 3059.79,1079.97 3163.51,976.25 3222.66,976.25 3303.24,895.67 3340.75,895.67 3347,889.42 v1(3350.39,889.42)
MGT_RXN3_225: J6.B15 MC3.35 | length 2796.5
  L1-Top w7.5: J6.B15@2427.16,137.79 2427.16,206.69 2412.41,221.44 2412.41,502.88 2544.17,634.64 2706.13,634.64 2886.07,814.58 2930.29,814.58 2936.88,807.98 2936.88,799.15 v1(2939.27,796.75) ; v1(2810.25,899.36) 2809.34,900.26 2809.34,908.24 2781.92,935.67 2781.92,1855.58 3173.25,2246.91 3196.93,2246.91 3198.41,2248.38 3229.08,2248.38 MC3.35@3230.7,2250
  L4-BOT w7.5: v1(2810.25,899.36) 2812.64,896.97 2822.13,896.97 2859.83,859.26 2885.6,859.26 2936.88,807.98 2936.88,799.15 v1(2939.27,796.75)
MGT_RXN3_226: J1.B12 MC3.55 | length 1035.6
  L1-Top w5.25: v1(2504.63,2801.48) 2507.71,2801.48 2515.08,2794.1 2825.44,2794.1 2881.63,2737.91 3201.71,2737.91 3202.64,2738.84 3227.42,2738.84 MC3.55@3230.7,2742.12
  L4-BOT w5.25: J1.B12@2296.96,2867.22 2296.96,2798.25 2301.11,2794.1 2425.59,2794.1 2494.18,2794.1 2501.56,2801.48 v1(2504.63,2801.48)
MGT_RXP0_224: J6.B45 MC3.1 | length 2004.9
  L1-Top w7.5: MC3.1@3230.7,1757.87 3229.08,1759.49 3198.41,1759.49 3196.93,1760.97 3179.02,1760.97 3162.45,1744.39 3162.45,1689.01 3244.63,1606.83 3247.28,1604.18 3268.76,1582.7 ccw(c3274.06,1588) 3279.36,1582.7 3282.02,1585.36 cw(c3285.91,1581.47) 3289.8,1585.36 3301.47,1573.69 cw(c3297.58,1569.81) 3301.47,1565.92 3298.81,1563.26 ccw(c3304.11,1557.95) 3298.81,1552.65 3318.25,1533.2 3320.91,1530.55 3502.25,1349.21 3502.25,1284.43 3508.5,1278.18 v1(3508.5,1275.59) ; J6.B45@3608.26,137.79 3608.26,206.69 3621.2,219.63 3621.2,240.7 3621.2,386.5 3637.29,402.6 3637.29,518.55 3583.16,572.68 3583.16,1015.92 3600.7,1033.47 3631.88,1033.47 3638.13,1039.72 v1(3638.38,1039.72)
  L4-BOT w7.5: v1(3508.5,1275.59) 3508.5,1272.21 3502.25,1265.96 3502.25,1248.79 3535.82,1215.21 3535.82,1114.34 3616.7,1033.47 3628.75,1033.47 3635,1039.72 v1(3638.38,1039.72)
MGT_RXP0_225: J6.B27 MC3.21 | length 2536.8
  L1-Top w7.5: J6.B27@2899.6,137.79 2899.6,206.69 2912.53,219.63 2912.53,240.7 2912.53,396.43 2935.06,418.96 2935.06,508.28 2941.73,514.96 2944.39,517.61 ccw(c2939.08,522.91) 2944.39,528.22 2941.72,530.88 cw(c2945.61,534.77) 2941.72,538.66 2953.39,550.32 cw(c2957.28,546.44) 2961.17,550.32 2963.83,547.66 ccw(c2969.13,552.97) 2974.44,547.66 2998.33,571.55 3010.44,583.66 3066.99,583.66 3222.18,738.85 3222.18,852.94 3244.56,875.32 3262.8,875.32 3269.05,881.57 v1(3272.43,881.57) ; v1(2968.81,1069.47) 2966.5,1071.78 2957.66,1071.78 2920.94,1108.5 2920.94,1810.04 3167.14,2056.24 3196.93,2056.24 3198.41,2054.77 3229.08,2054.77 MC3.21@3230.7,2053.15
  L4-BOT w7.5: v1(2968.81,1069.47) 2971.2,1067.08 2971.2,1058.24 3099.88,929.56 3164.38,929.56 3218.62,875.32 3262.8,875.32 3269.05,881.57 v1(3272.43,881.57)
MGT_RXP0_226: J1.B05 MC3.41 | length 1394.6
  L1-Top w5.25: v1(2504.63,1830.59) 2507.71,1830.59 2515.08,1837.97 2548.49,1837.97 2582.8,1872.28 2582.8,2021.78 3110.52,2549.49 3201.71,2549.49 3202.64,2548.55 3227.42,2548.55 MC3.41@3230.7,2545.27
  L4-BOT w5.25: J1.B05@2296.96,1764.85 2296.96,1833.82 2301.11,1837.97 2420.93,1837.97 2494.18,1837.97 2501.56,1830.59 v1(2504.63,1830.59)
MGT_RXP1_224: J6.B41 MC3.5 | length 2039.9
  L1-Top w7.5: MC3.5@3230.7,1816.93 3229.08,1818.55 3198.41,1818.55 3196.93,1820.02 3172.43,1820.02 3112.29,1759.89 3112.29,1635.62 3133.31,1614.61 3135.96,1611.95 3152.52,1595.4 ccw(c3157.82,1600.7) 3163.12,1595.4 3165.78,1598.06 cw(c3169.67,1594.17) 3173.56,1598.06 3185.23,1586.39 cw(c3181.34,1582.5) 3185.23,1578.61 3182.57,1575.95 ccw(c3187.87,1570.65) 3182.57,1565.35 3202.01,1545.9 3204.67,1543.25 3450.35,1297.57 3450.35,1121.06 3456.6,1114.81 v1(3456.6,1111.43) ; J6.B41@3450.78,137.79 3450.78,206.69 3463.71,219.63 3463.71,240.7 3463.71,396.2 3483.87,416.35 3483.87,980.22 3501.4,997.75 3524.03,997.75 3530.28,1004 v1(3533.67,1004)
  L4-BOT w7.5: v1(3456.6,1111.43) 3456.6,1108.05 3450.35,1101.8 3450.35,1059.39 3511.99,997.75 3524.03,997.75 3530.28,1004 v1(3533.67,1004)
MGT_RXP1_225: J6.B23 MC3.25 | length 2606.5
  L1-Top w7.5: J6.B23@2742.12,137.79 2742.12,206.69 2755.05,219.63 2755.05,240.7 2755.05,389.09 2779.06,413.1 2779.06,494.02 2811.81,526.77 2814.46,529.42 ccw(c2809.16,534.73) 2814.46,540.03 2811.8,542.69 cw(c2815.69,546.58) 2811.8,550.47 2823.47,562.14 cw(c2827.36,558.25) 2831.25,562.14 2833.91,559.47 ccw(c2839.21,564.78) 2844.52,559.47 2871.85,586.81 2971.16,686.12 3071.5,686.12 3120.35,734.97 3120.35,803.82 3138.49,821.96 3160.04,821.96 3166.29,828.21 v1(3169.67,828.21) 3169.67,826.36 v1@3165.28,821.96 ; v1(2966.85,979.32) 2966.5,979.68 2957.66,979.68 2879.03,1058.31 2879.03,1823.28 3171.04,2115.3 3196.93,2115.3 3198.41,2113.82 3229.08,2113.82 MC3.25@3230.7,2112.2
  L4-BOT w7.5: v1(2966.85,979.32) 2969.24,976.93 2969.24,968.09 3115.37,821.96 3160.04,821.96 3166.29,828.21 v1(3169.67,828.21)
MGT_RXP1_226: J1.B07 MC3.45 | length 1201
  L1-Top w5.25: v1(2504.63,2145.56) 2507.71,2145.56 2515.08,2152.93 2540.29,2152.93 2995.91,2608.55 3201.71,2608.55 3202.64,2607.61 3227.42,2607.61 MC3.45@3230.7,2604.33
  L4-BOT w5.25: J1.B07@2296.96,2079.81 2296.96,2148.78 2301.11,2152.93 2420.93,2152.93 2494.18,2152.93 2501.56,2145.56 v1(2504.63,2145.56)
